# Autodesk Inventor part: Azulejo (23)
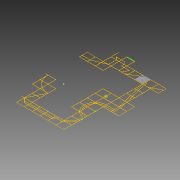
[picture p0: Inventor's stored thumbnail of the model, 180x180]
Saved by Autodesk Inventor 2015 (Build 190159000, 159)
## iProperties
Created: 2015-04
Part Number: Azulejo (23)
Material: Genérico
Document SubType Name: Modeling
Designer: Felipe
Density: 1 g/cm^3
Appearance: Padrão
Author: Felipe
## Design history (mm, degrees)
sketch "Sketch1"
  geometry: L1 (-1510, -7490)-(-1510, -6010); L2 (992.445, 7510)-(992.445, 8990); L3 (1012.445, 7510)-(1012.445, 8990); L4 (-3010, -1490)-(-3010, -10); L5 (-1510, 7490)-(-2990, 7490); L6 (-2990, 10)-(-1510, 10); L7 (-1510, -10)-(-2990, -10); L8 (-1510, -1490)-(-1510, -10); L9 (-10, 9010)-(-10, 10490); L10 (-10, 7510)-(-10, 8990); L11 (-10, 7490)-(-1490, 7490); L12 (-1490, 6010)-(-10, 6010); L13 (-10, 5990)-(-1490, 5990); L14 (-1490, -10)-(-1490, -1490); L15 (-1490, -1490)-(-10, -1490); L16 (-10, -1510)-(-1490, -1510); L17 (-10, -2990)-(-10, -1510); L18 (-10, -5990)-(-10, -4510); L19 (-1490, -7490)-(-10, -7490); L20 (10, 8990)-(10, 7510); L21 (1490, 7510)-(1490, 8990); L22 (10, 6010)-(1490, 6010); L23 (1490, 6010)-(1490, 7490); L24 (1490, 5990)-(10, 5990); L25 (4490, -6010)-(3010, -6010); L26 (10, -1510)-(10, -2990); L27 (10, -3010)-(10, -4490); L28 (10, -4510)-(10, -5990); L29 (10, -5990)-(1490, -5990); L30 (1490, -6010)-(10, -6010); L31 (10, -7490)-(1490, -7490); L32 (2990, 9010)-(2990, 10490); L33 (1510, 8990)-(1510, 7510); L34 (1510, 7510)-(2990, 7510); L35 (2990, 7490)-(1510, 7490); L36 (1510, 7490)-(1510, 6010); L37 (1510, -5990)-(2990, -5990); L38 (2990, -6010)-(1510, -6010); L39 (1510, -7490)-(2990, -7490); L40 (3010, 10490)-(3010, 9010); L41 (3010, 9010)-(4490, 9010); L42 (4490, 8990)-(3010, 8990); L43 (4490, 7490)-(3010, 7490); L44 (4490, 1510)-(4490, 2990); L45 (4490, 10)-(4490, 1490); L46 (4490, -1490)-(4490, -10); L47 (4490, -2990)-(4490, -1510); L48 (3010, -5990)-(4490, -5990); L49 (3010, -7490)-(4490, -7490); L50 (4510, 9010)-(5990, 9010); L51 (5990, 8990)-(4510, 8990); L52 (4510, 7510)-(5990, 7510); L53 (5990, 7490)-(4510, 7490); L54 (4510, 3010)-(5990, 3010); L55 (5990, 2990)-(4510, 2990); L56 (4510, 2990)-(4510, 1510); L57 (4510, 1510)-(5990, 1510); L58 (5990, 1510)-(5990, 1740.185); L59 (5990, 1760.2)-(5990, 2259.8); L60 (5990, 2279.815)-(5990, 2990); L61 (5990, 1490)-(4510, 1490); L62 (4510, 1490)-(4510, 10); L63 (4510, 10)-(5990, 10); L64 (5990, 10)-(5990, 1490)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; A1 r 250 centre (6000, 2010) between (5990, 2259.8) and (5990, 1760.2); A2 r 250 centre (6000, 2010) between (6010, 1760.2) and (6010, 2259.8); A3 r 270 centre (6000, 2010) between (5990, 2279.815) and (5990, 1740.185); A4 r 270 centre (6000, 2010) between (6010, 1740.185) and (6010, 2279.815); A5 r 3010.017 centre (0, 0) between (-1490, -2615.358) and (-346.554, -2990); A6 r 2990.017 centre (0, 0) between (-1490, -2592.316) and (-10, -2990); A7 r 3010.017 centre (0, 0) between (-2603.863, -1510) and (-1510, -2603.863); A8 r 2990.017 centre (0, 0) between (-2580.717, -1510) and (-1510, -2580.717); A9 r 3010.017 centre (0, 0) between (-2990, -346.554) and (-2615.358, -1490); A10 r 2990.017 centre (0, 0) between (-2990, -10) and (-2592.316, -1490); A11 r 2131.367 centre (7500, -1500) between (7490, 631.344) and (6010, 24.017); A12 r 2131.367 centre (7500, -1500) between (5975.983, -10) and (5368.656, -1490); A13 r 2131.367 centre (7500, -1500) between (5368.656, -1510) and (5975.983, -2990); A14 r 2131.367 centre (7500, -1500) between (6010, -3024.017) and (7190, -3608.703); A15 r 1831.367 centre (7500, -1500) between (7490.321, 331.342) and (6463.753, 10); A16 r 1831.367 centre (7500, -1500) between (6435.196, -10) and (6010, -435.196); A17 r 1831.367 centre (7500, -1500) between (5990, -463.753) and (5668.66, -1490); A18 r 1831.367 centre (7500, -1500) between (5668.66, -1510) and (5990, -2536.247); A19 r 1831.367 centre (7500, -1500) between (6010, -2564.804) and (6435.196, -2990); A20 r 1831.367 centre (7500, -1500) between (6463.753, -3010) and (7490, -3331.34); A21 r 2111.367 centre (7500, -1500) between (7490.047, 611.344) and (6024.272, 10); A22 r 2111.367 centre (7500, -1500) between (5990, -24.272) and (5388.656, -1490); A23 r 2111.367 centre (7500, -1500) between (5388.656, -1510) and (5990, -2975.728); A24 r 2111.367 centre (7500, -1500) between (6024.272, -3010) and (7210, -3591.357); A25 r 1811.367 centre (7500, -1500) between (7490.374, 311.342) and (6499.524, 10); A26 r 1811.367 centre (7500, -1500) between (6469.975, -10) and (6010, -469.975); A27 r 1811.367 centre (7500, -1500) between (5990, -499.524) and (5688.66, -1490); A28 r 1811.367 centre (7500, -1500) between (5688.66, -1510) and (5990, -2500.476); A29 r 1811.367 centre (7500, -1500) between (6010, -2530.025) and (6469.975, -2990); A30 r 1811.367 centre (7500, -1500) between (6499.524, -3010) and (7490, -3311.34); A31 r 449.871 centre (7499.449, -4060.672) between (7510, -4510.419) and (7521.546, -4510); 6 further points
  constraints: 1042 end point, 64 point on circle, 31 centre point, 13 point on line, 1 horizontal, 1 other
extrude "Extrusion1" new body sketch "Sketch1" distance "d0" = 60; taper "d1" = 0 deg
extrude "Extrusion2" new body sketch "Sketch1" distance "d2" = 60; taper "d3" = 0 deg
extrude "Extrusion3" new body sketch "Sketch1" distance "d4" = 60; taper "d5" = 0 deg
body "Solid1"
body "Solid2"
body "Solid3"
